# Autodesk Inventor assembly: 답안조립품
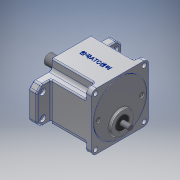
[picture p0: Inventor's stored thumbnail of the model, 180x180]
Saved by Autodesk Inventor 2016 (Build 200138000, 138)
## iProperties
Created: 2017-01
Part Number: 답안조립품
Material: 일반
Document SubType Name: Assembly
Designer: Owner
Author: Owner
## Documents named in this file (10)
- C:\Users\Owner\Desktop\470111V1004\답안조립품.iam
- C:\Users\Owner\Desktop\470111V1004\본체.ipt
- C:\Users\Owner\Desktop\470111V1004\메인축.ipt
- C:\Users\Owner\Desktop\470111V1004\베어링 608.ipt
- C:\Users\Owner\Desktop\470111V1004\베어링 6003.ipt
- C:\Users\Owner\Desktop\470111V1004\볼트 M4 x 10.ipt
- C:\Users\Owner\Desktop\470111V1004\서브축.ipt
- C:\Users\Owner\Desktop\470111V1004\오일실 8 22 7.ipt
- C:\Users\Owner\Desktop\470111V1004\오일실 17 32 8.ipt
- C:\Users\Owner\Desktop\470111V1004\커버.ipt
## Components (2 placed, 1 different names)
1. ISO 4762 M4 x 10:1
2. ISO 4762 M4 x 10:2
